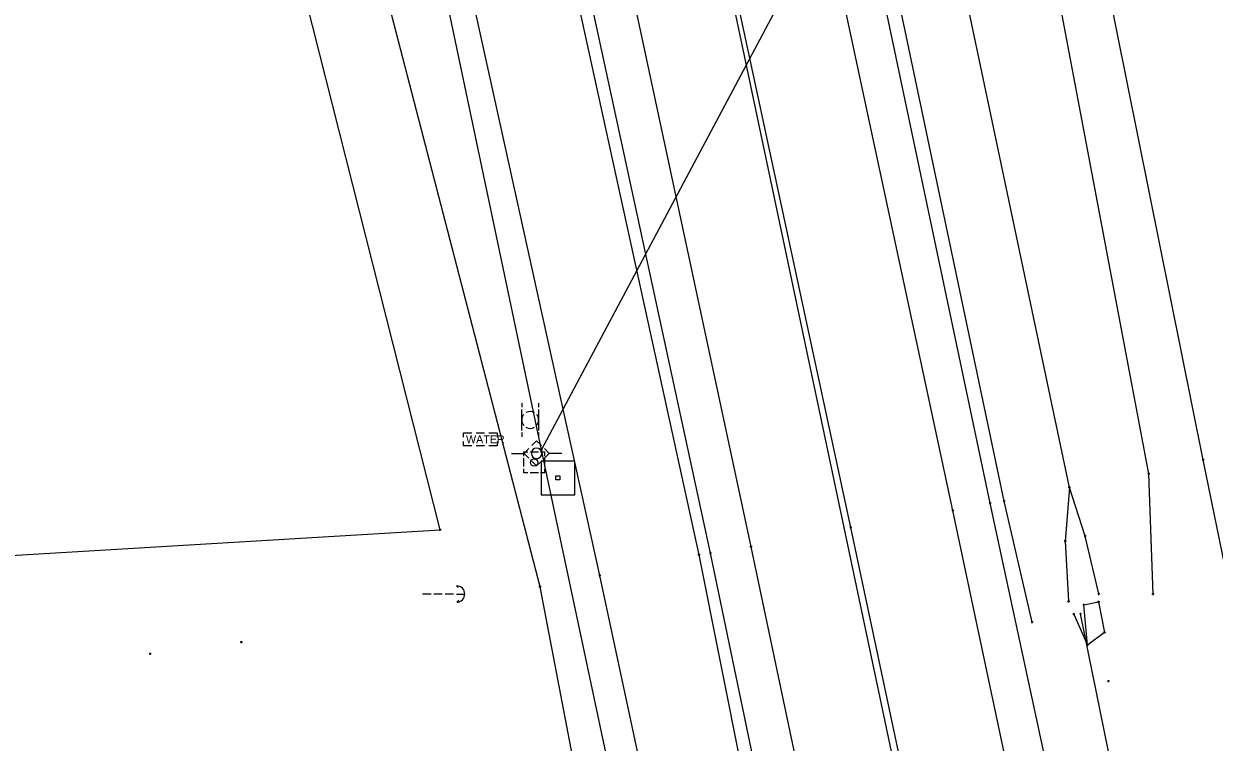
# Model space of a CAD drawing. Extents: x 1954856 to 2011933, y 399149 to 426294.
# Drawn here: x 2005312.9 to 2005454.3, y 405996.6 to 406081.9 of the extents above; entities that cross this region are included whole.
import ezdxf

# ---------------------------------------------------------------- set-up
doc = ezdxf.new("R2010")
doc.units = 0
for name, color, linetype in [('BankMent_ep', 7, 'Continuous'), ('BaselineSurvey', 7, 'Continuous'), ('DelineatorPost_ep', 7, 'Continuous'), ('ElecAer_ep', 7, 'Continuous'), ('EndTreatMES_ep', 7, 'Continuous'), ('Fence_ep', 7, 'Continuous'), ('FlowLineInvert_ep', 7, 'Continuous'), ('GuyWireAnchor_ep', 7, 'Continuous'), ('MeterWater_ep', 7, 'Continuous'), ('MonumentCC_ep', 7, 'Continuous'), ('PavtAsphalt_ep', 7, 'Continuous'), ('PavtAsphaltCrown_ep', 7, 'Continuous'), ('PipeCulvert_ep', 7, 'Continuous'), ('PointLocator_ep', 7, 'Continuous'), ('PoleShared_ep', 7, 'Continuous'), ('ShldrPaved_ep', 7, 'Continuous'), ('TelePed_ep', 7, 'Continuous'), ('TreeLineScatter_ep', 7, 'Continuous')]:
    doc.layers.add(name, color=color, linetype=linetype)

msp = doc.modelspace()

# ---------------------------------------------------------------- linework, layer by layer
at = {"layer": 'BankMent_ep'}
for p, q in [((2005446.53, 406028.46), (2005428.27, 406125)), ((2005429.35, 406025.19), (2005408.72, 406123.29)), ((2005393.12, 406018.84), (2005371.8, 406116.28)), ((2005374.24, 406015.03), (2005349.09, 406111.99)), ((2005447.03, 406014.16), (2005446.53, 406028.46)), ((2005412.76, 405920.6), (2005393.12, 406018.84))]:
    msp.add_line(p, q, dxfattribs=at)
for points in [[(2005437.09, 406026.84), (2005417.35, 406120.57), (2005414.72, 406130.56)], [(2005381.35, 406016.35), (2005359.9, 406113.76), (2005359.61, 406127.04)], [(2005440.61, 406014.17), (2005438.96, 406021.06), (2005437.09, 406026.84), (2005436.61, 406020.45), (2005437.01, 406013.28)], [(2005432.67, 406010.83), (2005429.35, 406025.19)], [(2005414.34, 405850.78), (2005402.21, 405918.91), (2005381.35, 406016.35)], [(2005400.35, 405883.04), (2005393.03, 405916.92), (2005374.24, 406015.03)]]:
    msp.add_lwpolyline(points, dxfattribs=at)
at = {"layer": 'BaselineSurvey'}
msp.add_line((2006223.92, 402174.38), (2005094.48, 407516.05), dxfattribs=at)
msp.add_line((2006223.92, 402174.38), (2005094.48, 407516.05), dxfattribs=at)
at = {"layer": 'DelineatorPost_ep'}
for p, q in [((2005372.07, 406036.85), (2005372.07, 406036.35)), ((2005374.07, 406036.85), (2005374.07, 406036.35)), ((2005372.07, 406033.6), (2005372.07, 406036.1)), ((2005374.07, 406036.1), (2005374.07, 406033.6)), ((2005373.07, 406034.85), (2005373.07, 406034.85)), ((2005372.07, 406033.35), (2005372.07, 406032.85)), ((2005374.07, 406033.35), (2005374.07, 406032.85))]:
    msp.add_line(p, q, dxfattribs=at)
for start, end in [(138.5904, 221.4096), (60, 120), (318.5904, 41.4096), (240, 300)]:
    msp.add_arc((2005373.07, 406034.85), 1, start, end, dxfattribs=at)
at = {"layer": 'ElecAer_ep'}
for points in [[(2005374.4, 406031.29), (2005312.74, 406324.27), (2005138.4, 406319.65)], [(2005445.5, 405696.72), (2005374.4, 406031.29), (2005427.33, 406130.78), (2005454.7, 406142.24)]]:
    msp.add_lwpolyline(points, dxfattribs=at)
at = {"layer": 'EndTreatMES_ep'}
msp.add_lwpolyline([(2005437.64, 406011.77), (2005439.26, 406008.09), (2005438.8, 406012.9), (2005440.57, 406013.23), (2005441.28, 406009.59), (2005439.26, 406008.09)], dxfattribs=at)
at = {"layer": 'Fence_ep'}
for points in [[(2005452.99, 406030.1), (2005432.43, 406132.27), (2005448.79, 406157.74), (2005453.81, 406158.81)], [(2005488.61, 405953.4), (2005468.8, 405952.83), (2005452.99, 406030.1)]]:
    msp.add_lwpolyline(points, dxfattribs=at)
at = {"layer": 'FlowLineInvert_ep'}
for p, q in [((2005438.49, 406011.73), (2005438.32, 406011.91)), ((2005438.49, 406011.91), (2005438.32, 406011.73)), ((2005438.41, 406011.82), (2005438.41, 406011.82))]:
    msp.add_line(p, q, dxfattribs=at)
at = {"layer": 'GuyWireAnchor_ep'}
for p, q in [((2005360.3, 406014.17), (2005361.3, 406014.17)), ((2005361.63, 406014.17), (2005362.63, 406014.17)), ((2005362.97, 406014.17), (2005363.97, 406014.17)), ((2005364.3, 406014.16), (2005365.3, 406014.16)), ((2005364.33, 406015.13), (2005364.52, 406014.94)), ((2005365.3, 406014.16), (2005365.3, 406014.16)), ((2005364.34, 406013.19), (2005364.58, 406013.42))]:
    msp.add_line(p, q, dxfattribs=at)
msp.add_arc((2005364.33, 406014.16), 0.973, 271.14, 90.0059, dxfattribs=at)
at = {"layer": 'MeterWater_ep'}
msp.add_line((2005367.14, 406032.55), (2005367.14, 406032.55), dxfattribs=at)
for points in [[(2005365.14, 406032.8), (2005365.14, 406033.3), (2005366.14, 406033.3)], [(2005366.64, 406033.3), (2005367.64, 406033.3)], [(2005368.14, 406033.3), (2005369.14, 406033.3), (2005369.14, 406032.8)], [(2005366.14, 406031.79), (2005365.14, 406031.79), (2005365.14, 406032.3)], [(2005367.64, 406031.79), (2005366.64, 406031.79)], [(2005369.14, 406032.3), (2005369.14, 406031.79), (2005368.14, 406031.79)]]:
    msp.add_lwpolyline(points, dxfattribs=at)
at = {"layer": 'MonumentCC_ep'}
msp.add_line((2005376.37, 406027.96), (2005376.37, 406027.96), dxfattribs=at)
msp.add_lwpolyline([(2005374.37, 406025.96), (2005378.37, 406025.96), (2005378.37, 406029.96), (2005374.37, 406029.96), (2005374.37, 406025.96)], dxfattribs=at)
msp.add_lwpolyline([(2005376.13, 406027.73), (2005376.13, 406028.2), (2005376.6, 406028.2), (2005376.6, 406027.73)], close=True, dxfattribs=at)
at = {"layer": 'PavtAsphalt_ep'}
for p, q in [((2005423.25, 406024.1), (2005402.21, 406122.25)), ((2005399.29, 406019.76), (2005378.35, 406117.8))]:
    msp.add_line(p, q, dxfattribs=at)
for points in [[(2005671.31, 404850.41), (2005650.51, 404948.22), (2005629.89, 405046.05), (2005609.27, 405144), (2005588.25, 405241.94), (2005567.84, 405339), (2005547.04, 405437.09), (2005526.5, 405535.12), (2005505.87, 405632.57), (2005485.22, 405730.46), (2005464.5, 405829.38), (2005444, 405926.25), (2005423.25, 406024.1)], [(2005647.53, 404845.36), (2005626.42, 404943.28), (2005605.83, 405041.29), (2005585.16, 405139.3), (2005564.57, 405237.07), (2005543.61, 405334.99), (2005527.25, 405416.17), (2005502.47, 405530.37), (2005481.58, 405628.35), (2005460.91, 405726.6), (2005440.43, 405824.02), (2005419.93, 405921.9), (2005399.29, 406019.76)]]:
    msp.add_lwpolyline(points, dxfattribs=at)
at = {"layer": 'PavtAsphaltCrown_ep'}
msp.add_line((2005411.14, 406022.06), (2005390.13, 406119.86), dxfattribs=at)
msp.add_lwpolyline([(2005659.53, 404847.95), (2005638.67, 404945.7), (2005617.91, 405043.69), (2005597.24, 405141.46), (2005576.51, 405239.3), (2005555.95, 405336.92), (2005535.17, 405434.82), (2005514.41, 405532.8), (2005493.56, 405630.59), (2005473.23, 405728.59), (2005452.36, 405826.42), (2005431.94, 405924.2), (2005411.14, 406022.06)], dxfattribs=at)
at = {"layer": 'PipeCulvert_ep'}
msp.add_lwpolyline([(2005449.35, 405958.09), (2005438.41, 406011.82)], dxfattribs=at)
at = {"layer": 'PointLocator_ep'}
for p, q in [((2005374.53, 406031.29), (2005374.28, 406031.29)), ((2005374.4, 406031.17), (2005374.4, 406031.42)), ((2005374.4, 406031.29), (2005374.4, 406031.29)), ((2005453.12, 406030.1), (2005452.87, 406030.1)), ((2005452.99, 406029.98), (2005452.99, 406030.23)), ((2005452.99, 406030.1), (2005452.99, 406030.1)), ((2005446.65, 406028.46), (2005446.4, 406028.46)), ((2005446.53, 406028.34), (2005446.53, 406028.59)), ((2005446.53, 406028.46), (2005446.53, 406028.46)), ((2005437.21, 406026.84), (2005436.96, 406026.84)), ((2005437.09, 406026.72), (2005437.09, 406026.97)), ((2005437.09, 406026.84), (2005437.09, 406026.84)), ((2005423.37, 406024.1), (2005423.12, 406024.1)), ((2005423.25, 406023.98), (2005423.25, 406024.23)), ((2005423.25, 406024.1), (2005423.25, 406024.1)), ((2005427.82, 406024.97), (2005427.57, 406024.97)), ((2005427.7, 406024.84), (2005427.7, 406025.09)), ((2005427.7, 406024.97), (2005427.7, 406024.97)), ((2005429.47, 406025.19), (2005429.22, 406025.19)), ((2005429.35, 406025.06), (2005429.35, 406025.31)), ((2005429.35, 406025.19), (2005429.35, 406025.19)), ((2005362.5, 406021.8), (2005362.25, 406021.8)), ((2005362.37, 406021.67), (2005362.37, 406021.92)), ((2005362.37, 406021.8), (2005362.37, 406021.8)), ((2005411.27, 406022.06), (2005411.02, 406022.06)), ((2005411.14, 406021.93), (2005411.14, 406022.18)), ((2005411.14, 406022.06), (2005411.14, 406022.06)), ((2005399.29, 406019.64), (2005399.29, 406019.89)), ((2005436.74, 406020.45), (2005436.49, 406020.45)), ((2005436.61, 406020.32), (2005436.61, 406020.57)), ((2005436.61, 406020.45), (2005436.61, 406020.45)), ((2005439.09, 406021.06), (2005438.84, 406021.06)), ((2005438.96, 406020.93), (2005438.96, 406021.18)), ((2005438.96, 406021.06), (2005438.96, 406021.06)), ((2005393.24, 406018.84), (2005392.99, 406018.84)), ((2005393.12, 406018.71), (2005393.12, 406018.96)), ((2005393.12, 406018.84), (2005393.12, 406018.84)), ((2005394.6, 406019.03), (2005394.35, 406019.03)), ((2005394.47, 406018.91), (2005394.47, 406019.16)), ((2005394.47, 406019.03), (2005394.47, 406019.03)), ((2005399.41, 406019.76), (2005399.16, 406019.76)), ((2005399.29, 406019.76), (2005399.29, 406019.76)), ((2005381.47, 406016.35), (2005381.22, 406016.35)), ((2005381.35, 406016.22), (2005381.35, 406016.47)), ((2005381.35, 406016.35), (2005381.35, 406016.35)), ((2005374.36, 406015.03), (2005374.11, 406015.03)), ((2005374.24, 406014.91), (2005374.24, 406015.16)), ((2005374.24, 406015.03), (2005374.24, 406015.03)), ((2005440.73, 406014.17), (2005440.48, 406014.17)), ((2005440.61, 406014.05), (2005440.61, 406014.3)), ((2005440.61, 406014.17), (2005440.61, 406014.17)), ((2005447.15, 406014.16), (2005446.9, 406014.16)), ((2005447.03, 406014.03), (2005447.03, 406014.28)), ((2005447.03, 406014.16), (2005447.03, 406014.16)), ((2005437.13, 406013.28), (2005436.88, 406013.28)), ((2005437.01, 406013.15), (2005437.01, 406013.4)), ((2005437.01, 406013.28), (2005437.01, 406013.28)), ((2005438.93, 406012.9), (2005438.68, 406012.9)), ((2005438.8, 406012.77), (2005438.8, 406013.02)), ((2005438.8, 406012.9), (2005438.8, 406012.9)), ((2005440.7, 406013.23), (2005440.45, 406013.23)), ((2005440.57, 406013.11), (2005440.57, 406013.36)), ((2005440.57, 406013.23), (2005440.57, 406013.23)), ((2005437.76, 406011.77), (2005437.51, 406011.77)), ((2005437.64, 406011.65), (2005437.64, 406011.9)), ((2005437.64, 406011.77), (2005437.64, 406011.77)), ((2005432.8, 406010.83), (2005432.55, 406010.83)), ((2005432.67, 406010.7), (2005432.67, 406010.95)), ((2005432.67, 406010.83), (2005432.67, 406010.83)), ((2005338.77, 406008.31), (2005338.77, 406008.56)), ((2005441.41, 406009.59), (2005441.16, 406009.59)), ((2005441.28, 406009.46), (2005441.28, 406009.71)), ((2005441.28, 406009.59), (2005441.28, 406009.59)), ((2005328.08, 406007.05), (2005327.83, 406007.05)), ((2005327.95, 406006.93), (2005327.95, 406007.18)), ((2005327.95, 406007.05), (2005327.95, 406007.05)), ((2005338.89, 406008.44), (2005338.64, 406008.44)), ((2005338.77, 406008.44), (2005338.77, 406008.44)), ((2005439.38, 406008.09), (2005439.13, 406008.09)), ((2005439.26, 406007.97), (2005439.26, 406008.22)), ((2005439.26, 406008.09), (2005439.26, 406008.09)), ((2005441.87, 406003.82), (2005441.62, 406003.82)), ((2005441.75, 406003.69), (2005441.75, 406003.94)), ((2005441.75, 406003.82), (2005441.75, 406003.82))]:
    msp.add_line(p, q, dxfattribs=at)
at = {"layer": 'PoleShared_ep'}
for p, q in [((2005372.35, 406030.88), (2005372.91, 406031.45)), ((2005370.85, 406030.88), (2005372.35, 406030.88)), ((2005372.91, 406030.32), (2005372.35, 406030.88)), ((2005373.83, 406030.88), (2005373.83, 406030.88)), ((2005376.82, 406030.88), (2005375.32, 406030.88))]:
    msp.add_line(p, q, dxfattribs=at)
for points in [[(2005373.27, 406031.81), (2005373.83, 406032.37), (2005374.4, 406031.81)], [(2005374.76, 406031.45), (2005375.32, 406030.88), (2005374.76, 406030.32)], [(2005374.4, 406029.96), (2005373.83, 406029.4), (2005373.27, 406029.96)]]:
    msp.add_lwpolyline(points, dxfattribs=at)
for start, end in [(90, 270), (270, 90)]:
    msp.add_arc((2005373.83, 406030.88), 0.625, start, end, dxfattribs=at)
at = {"layer": 'ShldrPaved_ep'}
for points in [[(2005427.7, 406024.97), (2005407.05, 406122.81), (2005403.17, 406140.91), (2005394.43, 406182.67), (2005386.26, 406221.03), (2005369.59, 406301.46), (2005360.38, 406345.51), (2005345.13, 406416.29), (2005324.23, 406514.8), (2005303.28, 406612.46), (2005282.99, 406710.33), (2005262.63, 406808.01), (2005242.11, 406905.6)], [(2005394.47, 406019.03), (2005373.39, 406116.63), (2005368.48, 406141.45), (2005353.83, 406211.62), (2005332.61, 406312.92), (2005327.02, 406337.91), (2005318.05, 406379.99), (2005311.74, 406410.14), (2005291.04, 406507.65), (2005270.49, 406605.83), (2005262.78, 406641.74), (2005258.18, 406663.71), (2005249.81, 406703.72), (2005229.26, 406801.09), (2005208.4, 406899.51)], [(2005661.01, 404921.05), (2005655.38, 404949.38), (2005634.67, 405046.77), (2005613.98, 405144.94), (2005594.72, 405236.59), (2005590.09, 405258.66), (2005572.53, 405339.95), (2005551.67, 405437.94), (2005530.81, 405538.07), (2005522.22, 405579.31), (2005511, 405633.61), (2005501.96, 405674.37), (2005495.79, 405704.21), (2005482.81, 405765.83), (2005476.98, 405793.67), (2005469.08, 405830.21), (2005448.74, 405927.16), (2005427.7, 406024.97)], [(2005642.79, 404844.43), (2005626.09, 404922.97), (2005619.59, 404953.5), (2005603.98, 405028.2), (2005595.2, 405068.87), (2005580.62, 405138.25), (2005559.73, 405235.86), (2005538.96, 405333.93), (2005522.84, 405410.17), (2005520.12, 405422.33), (2005518.17, 405431.54), (2005497.8, 405529.43), (2005476.92, 405627.44), (2005463.13, 405692.8), (2005451.37, 405749.13), (2005441.12, 405797.5), (2005431.89, 405841.86), (2005414.86, 405921.03), (2005394.47, 406019.03)]]:
    msp.add_lwpolyline(points, dxfattribs=at)
at = {"layer": 'TelePed_ep'}
for p, q in [((2005372.3, 406031.05), (2005372.8, 406031.05)), ((2005372.3, 406030.55), (2005372.3, 406031.05)), ((2005372.3, 406029.3), (2005372.3, 406030.3)), ((2005373.05, 406031.05), (2005374.05, 406031.05)), ((2005373.55, 406029.8), (2005373.55, 406029.8)), ((2005374.3, 406031.05), (2005374.8, 406031.05)), ((2005374.8, 406030.55), (2005374.8, 406031.05)), ((2005374.8, 406029.3), (2005374.8, 406030.3)), ((2005372.3, 406028.55), (2005372.3, 406029.05)), ((2005372.8, 406028.55), (2005372.3, 406028.55)), ((2005374.05, 406028.55), (2005373.05, 406028.55)), ((2005374.8, 406028.55), (2005374.3, 406028.55)), ((2005374.8, 406028.55), (2005374.8, 406029.05))]:
    msp.add_line(p, q, dxfattribs=at)
msp.add_circle((2005373.55, 406029.8), 0.438, dxfattribs=at)
at = {"layer": 'TreeLineScatter_ep'}
for points in [[(2005362.37, 406021.8), (2005340.02, 406110.24), (2005332.69, 406151.07)], [(2005223.3, 406013.47), (2005362.37, 406021.8)]]:
    msp.add_lwpolyline(points, dxfattribs=at)

# ---------------------------------------------------------------- texts
at = {"layer": 'MeterWater_ep'}
msp.add_text('WATER', height=0.95, dxfattribs=at).set_placement((2005365.45, 406032.07))

doc.saveas('drawing.dxf')
